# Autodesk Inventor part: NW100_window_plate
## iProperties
Shininess: 64.0
Length Units: 11269
Angle Units: 11279
Time Units: 11290
Mass Units: 11283
Length Display Precision: 3
Angle Display Precision: 2
Compacted: True
Part Number: NW100_window_plate
Document SubType Name: Modeling
Created: 2004-07
Designer: John Blackburn
Manufacturer: Standard
Standards Organization: Custom
Density: 0.0
Volumn: 0.0
Area: 0.0
PropertySet Name: Model Information
Control State: 0
Master: False
Checked Out: False
Author: John Blackburn
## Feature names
1. Extrusion1
